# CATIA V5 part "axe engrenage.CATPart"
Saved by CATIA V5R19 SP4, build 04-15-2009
Part number: axe engrenage
Bounding box of the stored display mesh (mm): x 0 to 84.21, y 12.516 to 43.526, z -12.161 to 18.849
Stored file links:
  G:\EU_thinkMotion\CFAO_2010\MMS_groupe1\MMS_groupe1\A reprendre\OK\rdeneffle\axe engrenage.CATPart
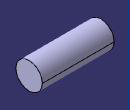
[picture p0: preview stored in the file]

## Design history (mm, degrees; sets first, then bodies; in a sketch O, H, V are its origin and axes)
Parameters
  `rayon axe engrenage` = 31.01 mm
Body1 (main body)
  Sketch1 on yz-plane, origin (0, 0, 0), H (0, 1, 0), V (0, 0, 1)
    circle A1 centre (28.021, 3.3437) radius 15.505
    radius A1 = 15.505 {= `rayon axe engrenage` /2}
  Pad1: profile Sketch1, direction (1, 0, 0), length 84.21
